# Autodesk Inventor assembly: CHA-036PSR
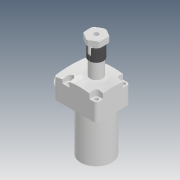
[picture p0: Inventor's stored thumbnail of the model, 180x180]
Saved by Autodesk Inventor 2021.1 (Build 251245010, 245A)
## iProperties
Created: 2018-12
Part Number: CHA-036PSR
Description: STEP AP214
Document SubType Name: Assembly
Designer: user
Title: CHA-036PSR.STEP
Revision Number: ÈÎºÎ
Sending System: SolidWorks 2016
Preprocessor: SwSTEP 2.0
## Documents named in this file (7)
- D:\Vault_2016\Projekty\Clamptek\Hydraulic\CHA-P\Inventor\CHA-036PSR\CHA-036PSR.iam
- D:\Vault_2016\Projekty\Clamptek\Hydraulic\CHA-P\Inventor\CHA-036PSR\CHA-036P(BT).ipt
- D:\Vault_2016\Projekty\Clamptek\Hydraulic\CHA-P\Inventor\CHA-036PSR\¶ÂÍ·G8-1.ipt
- D:\Vault_2016\Projekty\Clamptek\Hydraulic\CHA-P\Inventor\CHA-036PSR\CHA-036PS(ZH).ipt
- D:\Vault_2016\Projekty\Clamptek\Hydraulic\CHA-P\Inventor\CHA-036PSR\CHA-036PS(XIAO).ipt
- D:\Vault_2016\Projekty\Clamptek\Hydraulic\CHA-P\Inventor\CHA-036PSR\CHA-036PS(LM).ipt
- D:\Vault_2016\Projekty\Clamptek\Hydraulic\CHA-P\Inventor\CHA-036PSR\CHA-036PS(HSG).ipt
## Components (7 placed, 7 different names)
1. CHA-036P(BT)_1
2. ¶ÂÍ·G8-1_2
3. CHA-036PS(ZH)_3
4. CHA-036PS(XIAO)_4
5. ¶ÂÍ·G8-1_5
6. CHA-036PS(LM)_6
7. CHA-036PS(HSG)_7
